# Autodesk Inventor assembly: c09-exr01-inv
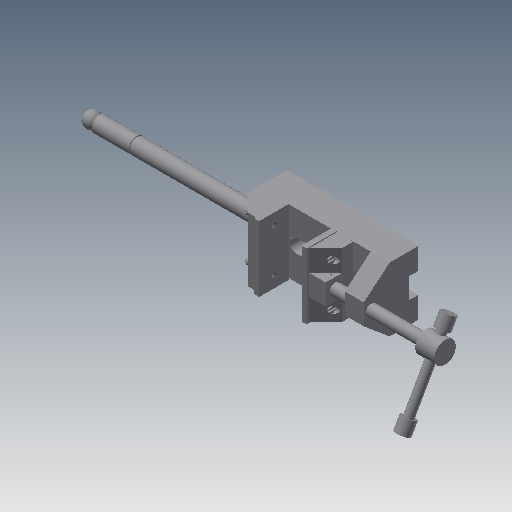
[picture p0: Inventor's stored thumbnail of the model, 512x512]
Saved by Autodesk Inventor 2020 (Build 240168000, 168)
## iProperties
Created: 2011-07
Part Number: c09-exr01-inv
Document SubType Name: Assembly
Designer: CadCim
Author: CadCim
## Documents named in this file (9)
- D:\Autodesk Inventor_2020\Resources\Resources\Inventor_2019_tut\Inventor_2019_tut\c13_Inv_2019_tut\c13_Inv_tut_2019\c13-tut02-inv\Drill Press vice\Drill Press Vice\c09-exr01-inv.iam
- D:\Autodesk Inventor_2020\Resources\Resources\Inventor_2019_tut\Inventor_2019_tut\c13_Inv_2019_tut\c13_Inv_tut_2019\c13-tut02-inv\Drill Press vice\Drill Press Vice\Base.ipt
- D:\Autodesk Inventor_2020\Resources\Resources\Inventor_2019_tut\Inventor_2019_tut\c13_Inv_2019_tut\c13_Inv_tut_2019\c13-tut02-inv\Drill Press vice\Drill Press Vice\Jaw Face.ipt
- D:\Autodesk Inventor_2020\Resources\Resources\Inventor_2019_tut\Inventor_2019_tut\c13_Inv_2019_tut\c13_Inv_tut_2019\c13-tut02-inv\Drill Press vice\Drill Press Vice\Movable Jaw.ipt
- D:\Autodesk Inventor_2020\Resources\Resources\Inventor_2019_tut\Inventor_2019_tut\c13_Inv_2019_tut\c13_Inv_tut_2019\c13-tut02-inv\Drill Press vice\Drill Press Vice\Safety Handle.ipt
- D:\Autodesk Inventor_2020\Resources\Resources\Inventor_2019_tut\Inventor_2019_tut\c13_Inv_2019_tut\c13_Inv_tut_2019\c13-tut02-inv\Drill Press vice\Drill Press Vice\Clamp Screw.ipt
- D:\Autodesk Inventor_2020\Resources\Resources\Inventor_2019_tut\Inventor_2019_tut\c13_Inv_2019_tut\c13_Inv_tut_2019\c13-tut02-inv\Drill Press vice\Drill Press Vice\Clamp Screw Handle.ipt
- D:\Autodesk Inventor_2020\Resources\Resources\Inventor_2019_tut\Inventor_2019_tut\c13_Inv_2019_tut\c13_Inv_tut_2019\c13-tut02-inv\Drill Press vice\Drill Press Vice\Handle Stop.ipt
- D:\Autodesk Inventor_2020\Resources\Resources\Inventor_2019_tut\Inventor_2019_tut\c13_Inv_2019_tut\c13_Inv_tut_2019\c13-tut02-inv\Drill Press vice\Drill Press Vice\Cap Screw.ipt
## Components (13 placed, 8 different names)
1. Base:1 — Insert:3, Insert:9, Insert:10, Mate:8, Mate:9, Mate:12, Mate:13
2. Jaw Face:1 — Mate:10, Mate:11, Mate:12
3. Movable Jaw:1 — Mate:3, Insert:4, Insert:11, Insert:12, Mate:9, Mate:13, Mate:15
4. Safety Handle:1 — Insert:3
5. Clamp Screw:1 — Mate:3, Insert:4, Mate:4, Mate:6, Mate:8
6. Clamp Screw Handle:1 — Mate:4, Insert:7, Insert:8
7. Jaw Face:2 — Mate:14, Mate:15
8. Handle Stop:1 — Insert:7, Mate:6
9. Handle Stop:2 — Insert:8
10. Cap Screw:1 — Insert:12
11. Cap Screw:2 — Insert:11, Mate:14
12. Cap Screw:3 — Insert:10, Mate:11
13. Cap Screw:4 — Insert:9, Mate:10
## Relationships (19: Mate 11, Insert 8)
- Insert:3: Base:1 ↔ Safety Handle:1
- Mate:3: Movable Jaw:1 ↔ Clamp Screw:1
- Insert:4: Movable Jaw:1 ↔ Clamp Screw:1
- Mate:4: Clamp Screw:1 ↔ Clamp Screw Handle:1
- Insert:7: Clamp Screw Handle:1 ↔ Handle Stop:1
- Insert:8: Clamp Screw Handle:1 ↔ Handle Stop:2
- Mate:6: Clamp Screw:1 ↔ Handle Stop:1
- Insert:9: Base:1 ↔ Cap Screw:4
- Insert:10: Base:1 ↔ Cap Screw:3
- Insert:11: Movable Jaw:1 ↔ Cap Screw:2
- Insert:12: Movable Jaw:1 ↔ Cap Screw:1
- Mate:8: Base:1 ↔ Clamp Screw:1
- Mate:9: Base:1 ↔ Movable Jaw:1
- Mate:10: Jaw Face:1 ↔ Cap Screw:4
- Mate:11: Jaw Face:1 ↔ Cap Screw:3
- Mate:12: Base:1 ↔ Jaw Face:1
- Mate:13: Base:1 ↔ Movable Jaw:1
- Mate:14: Jaw Face:2 ↔ Cap Screw:2
- Mate:15: Movable Jaw:1 ↔ Jaw Face:2
